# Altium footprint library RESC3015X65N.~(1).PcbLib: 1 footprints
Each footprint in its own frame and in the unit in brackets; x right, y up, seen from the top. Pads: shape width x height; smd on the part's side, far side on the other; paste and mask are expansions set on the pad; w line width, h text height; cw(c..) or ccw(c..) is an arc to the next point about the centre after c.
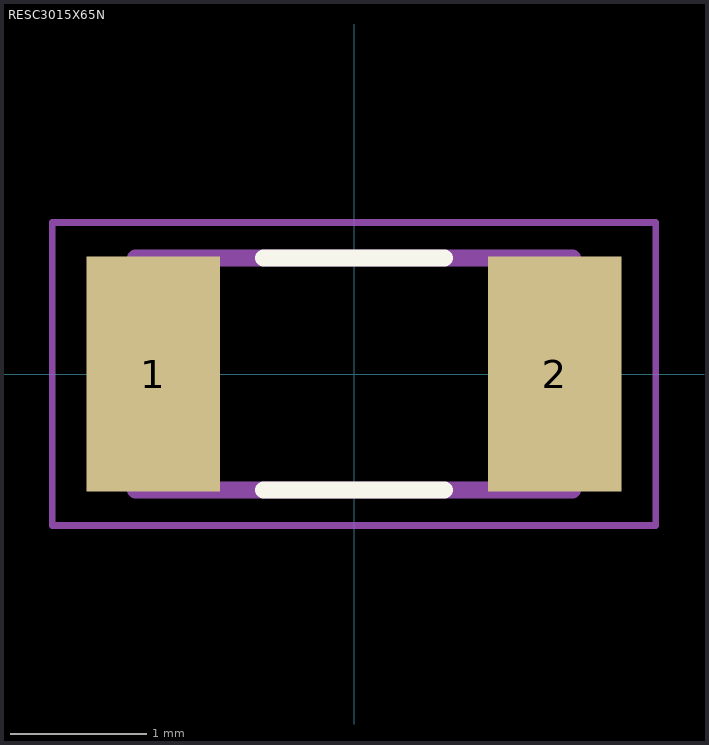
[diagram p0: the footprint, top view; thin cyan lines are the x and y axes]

## RESC3015X65N [mm]
pads (2):
  rect 0.98x1.72 smd: 1(-1.47,0) 2(1.47,0)
Top Overlay:
  lines w0.127: -0.66,-0.85 0.66,-0.85 ; -0.66,0.85 0.66,0.85
Mechanical 13:
  lines w0.127: -1.6,-0.85 1.6,-0.85 1.6,0.85 -1.6,0.85 -1.6,-0.85
Mechanical 15:
  lines w0.05: -2.21,-1.11 2.21,-1.11 2.21,1.11 -2.21,1.11 -2.21,-1.11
